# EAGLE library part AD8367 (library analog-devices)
500 MHz, Linear-in-dB VGA with AGC Detector Source: http://www.analog.com/UploadedFiles/Data_Sheets/477808511AD8367_a.pdf
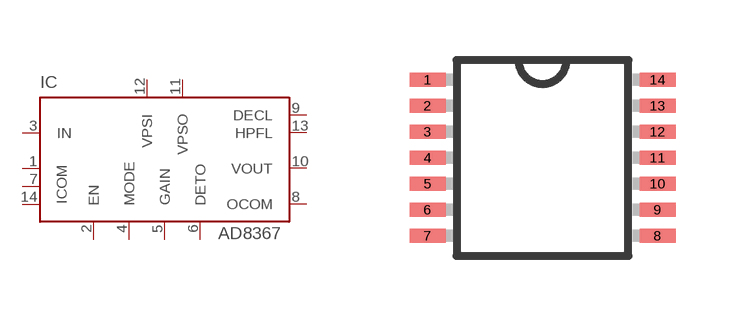
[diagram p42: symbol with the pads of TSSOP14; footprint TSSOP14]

Designator prefix IC

## AD8367RU (MF: ALTERA CORPORATION; MPN: AD8367ARUZ-RL7; OC_FARNELL: 1424121; OC_NEWARK: 59K6673)  [TSSOP14]
1  ICOM  pwr
2  EN  in
3  IN  in
4  MODE  in
5  GAIN  in
6  DETO  out
7  ICOM  pwr
8  OCOM  pwr
9  DECL  out
10  VOUT  out
11  VPSO  pwr
12  VPSI  pwr
13  HPFL  in
14  ICOM  pwr

## Footprint TSSOP14 (pad centres in mm)
14-Lead Thin Shrink Small Outline Package [TSSOP] Source: Analog Devices .. 780914713ADD8704_0.pdf
smd 0.9 x 0.35: 1 -2.875,1.95; 2 -2.875,1.3; 3 -2.875,0.65; 4 -2.875,0; 5 -2.875,-0.65; 6 -2.875,-1.3; 7 -2.875,-1.95; 8 2.875,-1.95; 9 2.875,-1.3; 10 2.875,-0.65; 11 2.875,0; 12 2.875,0.65; 13 2.875,1.3; 14 2.875,1.95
